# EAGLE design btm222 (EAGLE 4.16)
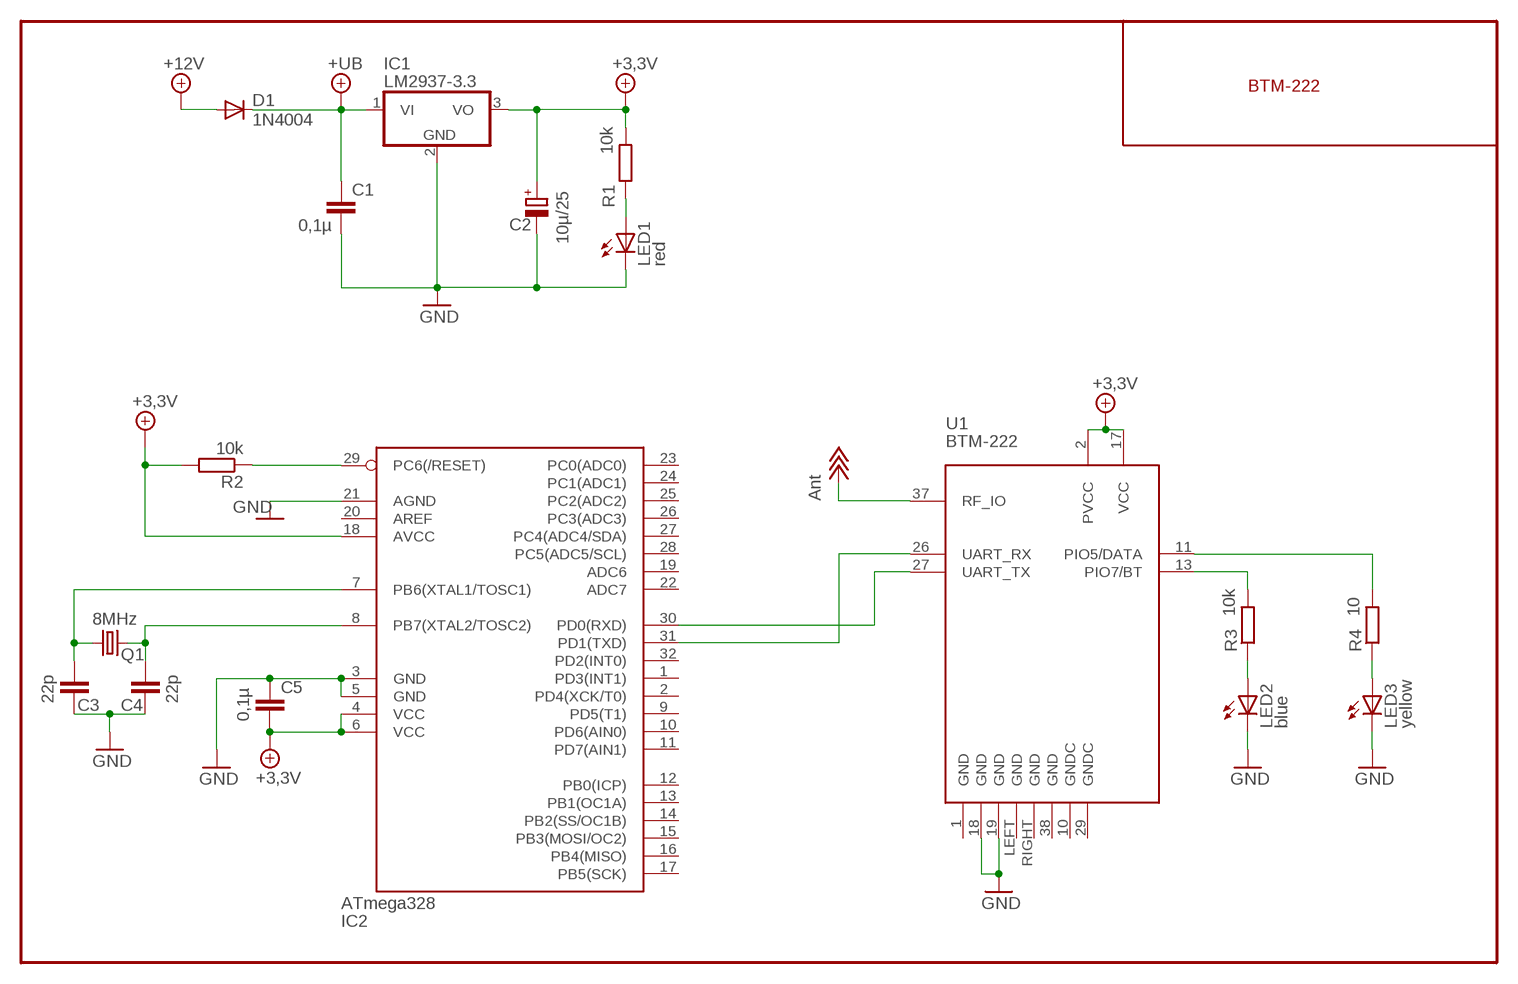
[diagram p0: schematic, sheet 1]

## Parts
C1  0,1µ  C-EUC1206  [C1206]
C2  10µ/25  CPOL-EU153CLV-0605  [153CLV-0605]
C3  22p  C-EUC1206  [C1206]
C4  22p  C-EUC1206  [C1206]
C5  0,1µ  C-EUC1206  [C1206]
D1  1N4004  DIODE-DO214AA  [DO214AA]
IC1  LM2937-3.3  LM2937SOT223  [SOT223]
IC2  ATmega328  MEGA8-AI  [TQFP32-08]
LED1  red  LEDCHIPLED_1206  [CHIPLED_1206]
LED2  blue  LEDCHIPLED_1206  [CHIPLED_1206]
LED3  yellow  LEDCHIPLED_1206  [CHIPLED_1206]
Q1  8MHz  CRYTALSM49  [SM49]
R1  10k  R-EU_R1206  [R1206]
R2  10k  R-EU_R1206  [R1206]
R3  10k  R-EU_R1206  [R1206]
R4  10  R-EU_R1206  [R1206]
U1  BTM-222  [BTM-222]

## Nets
+3,3V: C2.+ C5.2 IC1.3(VO) IC2.4(VCC) IC2.6(VCC) IC2.18(AVCC) R1.2 R2.2 U1.2(PVCC) U1.17(VCC)
+12V: D1.A
+18V: U1.37(RF_IO) ; supply symbol labelled Ant
+UB: C1.1 D1.C IC1.1(VI)
GND: C1.2 C2.- C3.2 C4.2 C5.1 IC1.2(GND) IC1.4(GND1) IC2.3(GND) IC2.5(GND) IC2.21(AGND) LED1.C LED2.C LED3.C U1.18(GND) U1.19(GND)
N$1: LED2.A R3.1
N$3: IC2.29(PC6(/RESET)) R2.1
N$4: LED1.A R1.1
N$5: C3.1 IC2.7(PB6(XTAL1/TOSC1)) Q1.1
N$7: C4.1 IC2.8(PB7(XTAL2/TOSC2)) Q1.2
N$9: R3.2 U1.13(PIO7/BT)
N$13: LED3.A R4.1
N$14: R4.2 U1.11(PIO5/DATA)
N$18: IC2.31(PD1(TXD)) U1.26(UART_RX)
N$19: IC2.30(PD0(RXD)) U1.27(UART_TX)
Unconnected: IC2.1(PD3(INT1)) IC2.2(PD4(XCK/T0)) IC2.9(PD5(T1)) IC2.10(PD6(AIN0)) IC2.11(PD7(AIN1)) IC2.12(PB0(ICP)) IC2.13(PB1(OC1A)) IC2.14(PB2(SS/OC1B)) IC2.15(PB3(MOSI/OC2)) IC2.16(PB4(MISO)) IC2.17(PB5(SCK)) IC2.19(ADC6) IC2.20(AREF) IC2.22(ADC7) IC2.23(PC0(ADC0)) IC2.24(PC1(ADC1)) IC2.25(PC2(ADC2)) IC2.26(PC3(ADC3)) IC2.27(PC4(ADC4/SDA)) IC2.28(PC5(ADC5/SCL)) IC2.32(PD2(INT0))

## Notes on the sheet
- BTM-222

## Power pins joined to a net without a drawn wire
GND: U1.1(GND) U1.38(GND) U1.LEFT(GND) U1.RIGHT(GND)
GNDC: U1.10(GNDC) U1.29(GNDC)

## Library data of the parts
C1 C3-C5 = rcl:C-EU: CAPACITOR, European symbol
C2 = rcl:CPOL-EU: POLARIZED CAPACITOR, European symbol
D1 = diode:DIODE-: DIODE
IC1 = 0_my_lib:LM2937: LM2937-2.5, LM2937-3.3 400mA and 500mA Voltage Regulators Source: http://cache.national.com/ds/LM/LM2937-2.5.pdf
IC2 = atmel:MEGA8: MICROCONTROLLER 8 Kbytes FLASH 1 kbytes SRAM 512 bytes EEPROM USART 6-channel 10 bit ADC 2-channel 8 bit ADC Source: avr.lbr
LED1-LED3 = led:LED: LED
Q1 = crystal:CRYTAL: CRYSTAL
R1-R4 = rcl:R-EU_: RESISTOR, European symbol
U1 = 0_my_lib:BTM-222

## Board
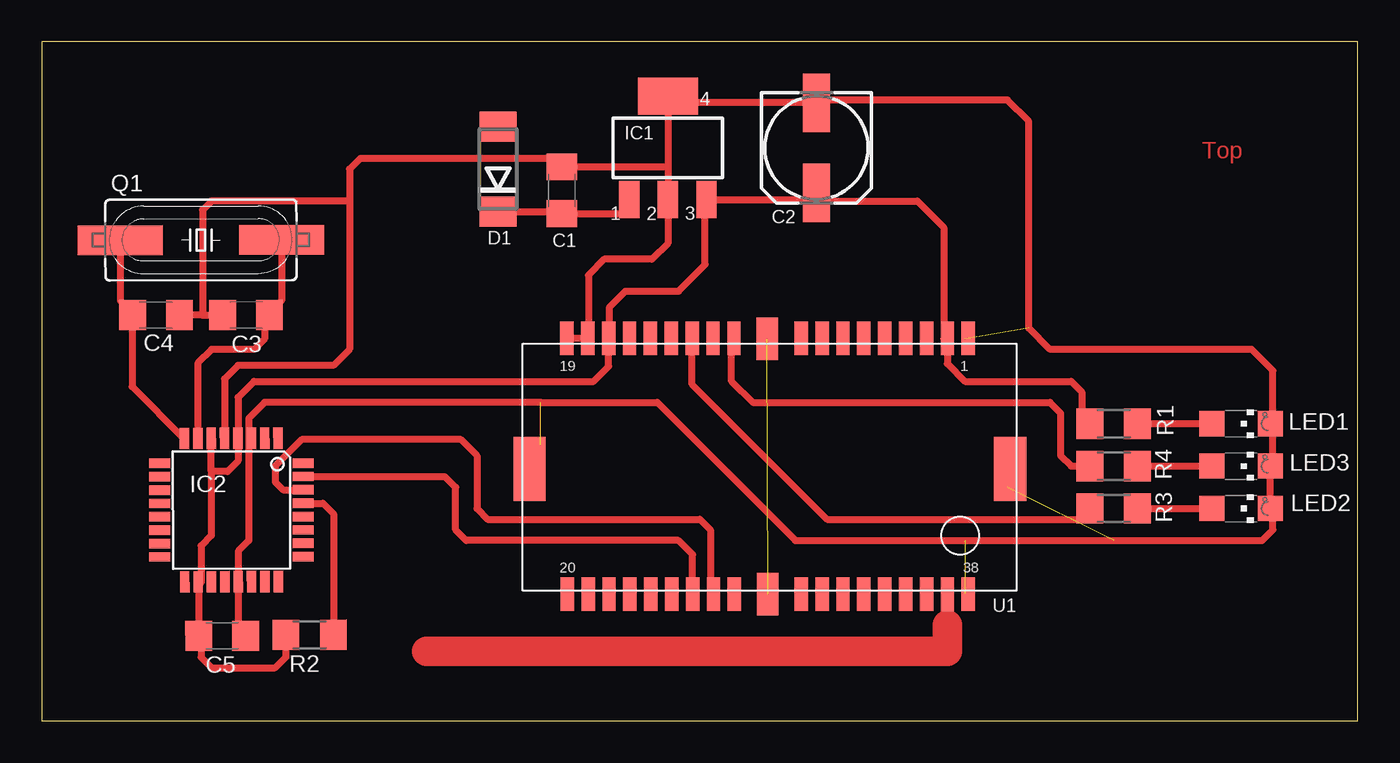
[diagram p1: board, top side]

Size 78.74 x 40.64 mm. Coordinates in mm from the lower left corner, seen from the top.
Outline: 0,0 78.74,0 78.74,40.64 0,40.64 0,0
Copper layers (1*16): Top 0.035mm / dielectric 1.5mm / Bottom 0.035mm
Design rules "default": minimum track width 10mil, minimum drill 0.3mm, track to track 0.15mm, track to pad 0.15mm, pad to pad 0.15mm, via to via 0.15mm, smd to smd 8mil, copper to edge 0.3mm, drill to drill 0.3mm, minimum pad ring 10mil, minimum via ring 8mil, stop-mask expansion 4mil, vias tented up to drill 40mil, thermal gap 10mil

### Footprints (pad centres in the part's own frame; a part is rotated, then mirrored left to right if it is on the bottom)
C1206 = smd 1.6 x 1.8: 1 -1.4,0; 2 1.4,0
153CLV-0605 = smd 3.5 x 1.6: + 2.7,0; - -2.7,0
DO214AA = smd 1.8 x 2.2: A 2.55,0; C -2.55,0
SOT223 = smd 1.219 x 2.235: 1 -2.311,-3.099; 2 0,-3.099; 3 2.311,-3.099 | smd 3.6 x 2.2: 4 0,3.099
TQFP32-08 = smd 1.27 x 0.559: 1 -4.293,2.8; 2 -4.293,2; 3 -4.293,1.2; 4 -4.293,0.4; 5 -4.293,-0.4; 6 -4.293,-1.2; 7 -4.293,-2; 8 -4.293,-2.8; 17 4.293,-2.8; 18 4.293,-2; 19 4.293,-1.2; 20 4.293,-0.4; 21 4.293,0.4; 22 4.293,1.2; 23 4.293,2; 24 4.293,2.8 | smd 0.559 x 1.27: 9 -2.8,-4.293; 10 -2,-4.293; 11 -1.2,-4.293; 12 -0.4,-4.293; 13 0.4,-4.293; 14 1.2,-4.293; 15 2,-4.293; 16 2.8,-4.293; 25 2.8,4.293; 26 2,4.293; 27 1.2,4.293; 28 0.4,4.293; 29 -0.4,4.293; 30 -1.2,4.293; 31 -2,4.293; 32 -2.8,4.293
CHIPLED_1206 = smd 1.5 x 1.5: A 0,-1.75; C 0,1.75
SM49 = smd 5.08 x 1.778: 1 -4.826,0; 2 4.826,0
R1206 = smd 1.6 x 1.803: 1 -1.422,0; 2 1.422,0
BTM-222 = smd 0.8 x 2: 1 0,-15.325; 2 1.25,-15.325; 3 2.5,-15.325; 4 3.75,-15.325; 5 5,-15.325; 6 6.25,-15.325; 7 7.5,-15.325; 8 8.75,-15.325; 9 10,-15.325; 11 14.021,-15.325; 12 15.271,-15.325; 13 16.521,-15.325; 14 17.771,-15.325; 15 19.021,-15.325; 16 20.271,-15.325; 17 21.521,-15.325; 18 22.771,-15.325; 19 24.021,-15.325; 20 23.996,0; 21 22.746,0; 22 21.496,0; 23 20.246,0; 24 18.996,0; 25 17.746,0; 26 16.496,0; 27 15.246,0; 28 13.996,0; 30 10,0; 31 8.75,0; 32 7.5,0; 33 6.25,0; 34 5,0; 35 3.75,0; 36 2.5,0; 37 1.25,0; 38 0,0 | smd 1.27 x 2.54: 10 12.036,-15.294; 29 12,0 | smd 1.93 x 3.81: LEFT -2.5,-7.5; RIGHT 26.25,-7.5

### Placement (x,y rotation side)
C1  31.11,31.75 90 top
C2  46.35,34.29 270 top
C3  12.22,24.29 180.1 top
C4  6.84,24.28 0.1 top
C5  10.79,5.08 180.1 top
D1  27.3,33.02 90 top
IC1  37.47,34.29 0 top
IC2  11.35,12.61 270.1 top
LED1  71.75,17.78 270 top
LED2  71.75,12.7 270 top
LED3  71.75,15.24 270 top
Q1  9.52,28.78 180.1 top
R1  64.14,17.78 180 top
R2  16.03,5.15 180.1 top
R3  64.14,12.7 180 top
R4  64.14,15.24 180 top
U1  55.44,7.57 180 top

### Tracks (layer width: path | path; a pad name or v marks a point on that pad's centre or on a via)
+3,3V
  Top 0.406: 46.35,31.19 C2.+ | 46.35,31.19 IC1.3 39.7,31.11 39.69,31.11 39.69,27.3 38.1,25.72 34.92,25.72 33.97,24.77 33.97,22.89 U1.17 33.92,21.22 33.02,20.32 12.7,20.32 11.74,19.36 IC2.4 11.74,15.55 11.11,14.92 10.14,14.92 | 46.35,31.19 46.35,31.11 52.39,31.11 53.98,29.53 53.98,22.86 54.01,22.89 U1.2 54.19,21.38 55.24,20.32 61.59,20.32 62.23,19.68 62.23,17.78 R1.2 | 10.14,14.92 IC2.6 | 10.14,14.92 10.14,11.09 9.53,10.48 9.53,8.26 | 9.53,8.26 9.46,8.32 IC2.18 | 9.53,8.26 9.39,8.12 C5.2 9.52,5.08 9.53,5.08 9.53,3.81 10.16,3.17 13.97,3.17 14.61,3.81 R2.2
+UB
  Top 0.406: 31.11,30.47 C1.1 34.92,30.35 34.92,30.48 | D1.C 31.11,30.47 | 31.11,30.47 31.11,30.48 | 34.92,30.48 34.92,31.75 | IC1.1 34.92,31.19 34.92,30.48
GND  (4 unrouted)
  Top 0.254: 55.24,7.62 U1.38 | 55.24,22.86 U1.1 | U1.RIGHT 29.84,16.51 | 57.78,13.97 U1.LEFT
  Top 0.406: 37.47,33.15 C1.2 31.11,33.02 30.48,33.66 19.05,33.66 18.41,33.02 18.41,31.11 | 37.47,33.15 IC1.2 37.47,28.57 36.51,27.62 33.66,27.62 32.7,26.67 32.7,22.86 U1.18 | 37.47,37.47 IC1.4 37.47,36.83 | 37.47,36.83 37.47,33.15 | 37.47,36.83 37.47,36.99 C2.- 46.35,36.83 46.67,37.15 57.78,37.15 59.05,35.88 59.05,23.5 60.33,22.23 72.39,22.23 73.66,20.95 73.66,17.78 | U1.18 | U1.18 U1.19 | C3.2 10.82,24.16 10.79,24.13 10.64,24.28 9.62,24.28 | 9.62,24.28 C4.2 | C5.1 12.07,5.08 12.06,5.08 11.76,5.39 IC2.21 11.76,10.17 12.38,10.79 12.38,16.83 | 12.38,16.83 12.46,16.91 IC2.3 | 9.62,24.28 9.62,30.57 10.16,31.11 18.41,31.11 | IC2.5 10.94,20.46 11.75,21.27 17.46,21.27 18.41,22.23 18.41,31.11 | 73.66,15.24 73.5,15.09 LED2.C 73.66,12.7 73.66,11.43 73.03,10.79 64.14,10.79 55.24,10.79 45.09,10.79 36.83,19.05 29.84,19.05 13.34,19.05 12.38,18.1 12.38,16.83 | 73.66,15.24 LED3.C | 73.66,17.78 LED1.C | 73.66,15.24 73.66,17.78
GNDC  (1 unrouted)
N$1
  Top 0.406: R3.1 LED2.A
N$3
  Top 0.406: 15.56,13.02 IC2.29 16.82,13.02 17.46,12.38 17.46,5.4 17.71,5.15 | 17.71,5.15 17.78,5.08 | 17.71,5.15 R2.1
N$4
  Top 0.406: 70.48,17.78 LED1.A R1.1
N$5
  Top 0.406: 13.5,24.29 13.34,24.13 13.34,22.86 12.7,22.23 10.16,22.23 9.34,21.41 IC2.7 | 13.5,24.29 C3.1 | Q1.1 14.35,25.14 13.5,24.29
N$6
  Top 0.61: 54.18,6.29 54.2,6.25
  Top 0.813: 54.18,6.29 54.18,7.29
N$7
  Top 0.406: 5.57,24.28 5.71,24.13 | 5.57,24.28 C4.1 5.44,24.41 5.4,24.45 | Q1.2 4.7,25.15 5.4,24.45 | 5.4,24.45 5.57,24.28 | IC2.8 8.5,16.9 5.4,20 5.4,24.45
N$9
  Top 0.406: U1.13 38.92,20.14 46.99,12.06 62.23,12.06 62.87,12.7 R3.2
N$10
  Top 1.778: 23.03,4.15 54.03,4.15
N$11
  Top 1.778: 54.19,4.16 54.19,5.73
N$13
  Top 0.406: 70.48,15.24 LED3.A R4.1
N$14
  Top 0.406: R4.2 61.59,15.24 60.96,15.88 60.96,18.41 60.33,19.05 42.55,19.05 41.27,20.32 41.27,22.86 41.31,22.89 U1.11
N$18
  Top 0.406: U1.26 38.94,9.95 38.1,10.79 25.4,10.79 24.77,11.43 24.77,13.97 24.13,14.61 15.88,14.61 15.86,14.62 IC2.31
N$19
  Top 0.406: 40.16,7.62 40.19,7.59 U1.27 40.06,7.57 40.01,7.62 40.01,11.43 39.37,12.06 26.67,12.06 26.04,12.7 26.04,15.88 25.08,16.83 15.56,16.83 13.97,15.24 13.97,14.29 14.44,13.82 IC2.30

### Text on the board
Top: Top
